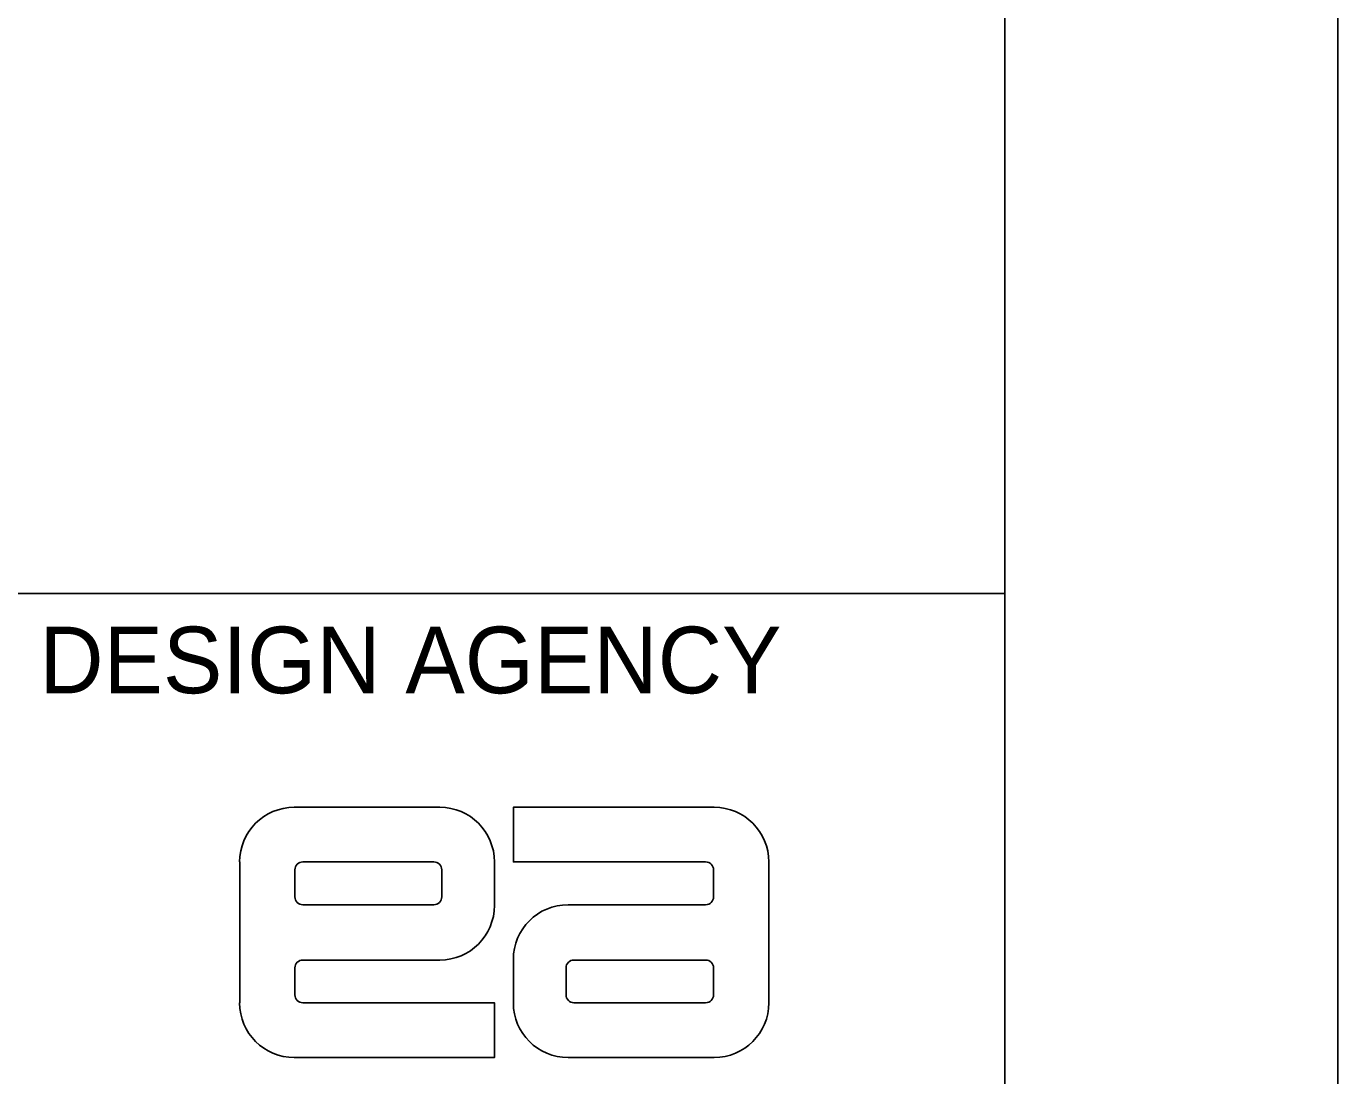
# Model space of a CAD drawing. Extents: x 0 to 34, y 0 to 25.2.
# Drawn here: x 32.03 to 34, y 3.776 to 5.352 of the extents above; entities that cross this region are included whole.
import ezdxf

# ---------------------------------------------------------------- set-up
doc = ezdxf.new("R2010")
doc.units = 0
for name, color, linetype in [('SH_Border', 7, 'Continuous'), ('SH_Cut_Line', 7, 'Continuous'), ('SH_Data', 7, 'Continuous'), ('TX_X_20', 7, 'Continuous')]:
    doc.layers.add(name, color=color, linetype=linetype)

msp = doc.modelspace()

# ---------------------------------------------------------------- linework, layer by layer
at = {"layer": 'SH_Border'}
msp.add_line((32, 4.5), (33.5, 4.5), dxfattribs=at)
msp.add_lwpolyline([(1.5, 21.5), (33.5, 21.5), (33.5, 0.5), (1.5, 0.5)], close=True, dxfattribs=at)
at = {"layer": 'SH_Cut_Line'}
msp.add_lwpolyline([(0, 0), (34, 0), (34, 22), (0, 22)], close=True, dxfattribs=at)
at = {"layer": 'TX_X_20'}
for p, q in [((32.6515, 4.1788), (32.433, 4.1788)), ((32.433, 4.1788), (32.6515, 4.1788)), ((32.762, 4.1788), (33.0635, 4.1788)), ((32.762, 4.0967), (32.762, 4.1788)), ((32.351, 4.0967), (32.351, 3.8852)), ((32.351, 3.8852), (32.351, 4.0967)), ((32.4459, 4.0967), (32.6426, 4.0967)), ((32.6426, 4.0967), (32.4459, 4.0967)), ((32.7336, 4.0315), (32.7336, 4.0967)), ((32.7336, 4.0967), (32.7336, 4.0315)), ((33.0507, 4.0967), (32.762, 4.0967)), ((33.1456, 3.8852), (33.1456, 4.0967)), ((33.1456, 4.0967), (33.1456, 3.8852)), ((32.434, 4.0444), (32.434, 4.0849)), ((32.434, 4.0849), (32.434, 4.0444)), ((32.6545, 4.0849), (32.6545, 4.0444)), ((32.6545, 4.0444), (32.6545, 4.0849)), ((33.0626, 4.0849), (33.0626, 4.0444)), ((33.0626, 4.0444), (33.0626, 4.0849)), ((32.6426, 4.0325), (32.4459, 4.0325)), ((32.4459, 4.0325), (32.6426, 4.0325)), ((33.0507, 4.0325), (32.8441, 4.0325)), ((32.8441, 4.0325), (33.0507, 4.0325)), ((32.4459, 3.9494), (32.6515, 3.9494)), ((32.6515, 3.9494), (32.4459, 3.9494)), ((32.762, 3.9504), (32.762, 3.8852)), ((32.762, 3.8852), (32.762, 3.9504)), ((32.853, 3.9494), (33.0507, 3.9494)), ((33.0507, 3.9494), (32.853, 3.9494)), ((32.434, 3.8971), (32.434, 3.9376)), ((32.434, 3.9376), (32.434, 3.8971)), ((32.8411, 3.8971), (32.8411, 3.9376)), ((32.8411, 3.9376), (32.8411, 3.8971)), ((33.0626, 3.9376), (33.0626, 3.8971)), ((33.0626, 3.8971), (33.0626, 3.9376)), ((32.4459, 3.8852), (32.7336, 3.8852)), ((32.7336, 3.8852), (32.7336, 3.8031)), ((33.0507, 3.8852), (32.853, 3.8852)), ((32.853, 3.8852), (33.0507, 3.8852)), ((32.7336, 3.8031), (32.433, 3.8031)), ((32.8441, 3.8031), (33.0635, 3.8031)), ((33.0635, 3.8031), (32.8441, 3.8031))]:
    msp.add_line(p, q, dxfattribs=at)
for points in [[(33.0635, 4.1788), (32.762, 4.1788), (32.762, 4.0967), (33.0507, 4.0967)], [(32.433, 3.8031), (32.7336, 3.8031), (32.7336, 3.8852), (32.4459, 3.8852)]]:
    msp.add_lwpolyline(points, dxfattribs=at)
for centre, radius, start, end in [((32.433, 4.0967), 0.0821, 90, 180), ((32.433, 4.0967), 0.0821, 90, 180), ((32.6515, 4.0967), 0.0821, 0, 90), ((32.6515, 4.0967), 0.0821, 0, 90), ((33.0635, 4.0967), 0.0821, 0, 90), ((33.0635, 4.0967), 0.0821, 0, 90), ((32.4459, 4.0849), 0.0119, 90, 180), ((32.4459, 4.0849), 0.0119, 90, 180), ((32.6426, 4.0849), 0.0119, 0, 90), ((32.6426, 4.0849), 0.0119, 0, 90), ((33.0507, 4.0849), 0.0119, 0, 90), ((33.0507, 4.0849), 0.0119, 0, 90), ((32.4459, 4.0444), 0.0119, 180, 270), ((32.4459, 4.0444), 0.0119, 180, 270), ((32.6426, 4.0444), 0.0119, 270, 0), ((32.6426, 4.0444), 0.0119, 270, 0), ((33.0507, 4.0444), 0.0119, 270, 0), ((33.0507, 4.0444), 0.0119, 270, 0), ((32.6515, 4.0315), 0.0821, 270, 360), ((32.6515, 4.0315), 0.0821, 270, 360), ((32.8441, 3.9504), 0.0821, 90, 180), ((32.8441, 3.9504), 0.0821, 90, 180), ((32.4459, 3.9376), 0.0119, 90, 180), ((32.4459, 3.9376), 0.0119, 90, 180), ((32.853, 3.9376), 0.0119, 90, 180), ((32.853, 3.9376), 0.0119, 90, 180), ((33.0507, 3.9376), 0.0119, 0, 90), ((33.0507, 3.9376), 0.0119, 0, 90), ((32.433, 3.8852), 0.0821, 180, 270), ((32.433, 3.8852), 0.0821, 180, 270), ((32.4459, 3.8971), 0.0119, 180, 270), ((32.4459, 3.8971), 0.0119, 180, 270), ((32.8441, 3.8852), 0.0821, 180, 270), ((32.8441, 3.8852), 0.0821, 180, 270), ((32.853, 3.8971), 0.0119, 180, 270), ((32.853, 3.8971), 0.0119, 180, 270), ((33.0507, 3.8971), 0.0119, 270, 0), ((33.0507, 3.8971), 0.0119, 270, 0), ((33.0635, 3.8852), 0.0821, 270, 360), ((33.0635, 3.8852), 0.0821, 270, 360)]:
    msp.add_arc(centre, radius, start, end, dxfattribs=at)

# ---------------------------------------------------------------- texts
at = {"layer": 'SH_Data'}
msp.add_text('DESIGN AGENCY', height=0.1, dxfattribs=at).set_placement((32.05, 4.35))

doc.saveas('drawing.dxf')
